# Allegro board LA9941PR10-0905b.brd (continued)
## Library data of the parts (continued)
C11 C12 CA8 CA11 CA16 CA54-CA57 CA61 CA62 CA64 CA68 CA69 CA71-CA73 CA75 CA76 CA78 CA82 CA84 CE57 CE322 CH102 CM32 CN34 CT22 CV26 CV702 CV709 CV727 CV734 CV767 CZ28 CZ29 CZ32 CZ600 CZ601 PC108 PC209 PC212 PC216 PC224 PC261 PC307 PC310 PC311 PC316 PC317 PC319 PC404 PC407 PC409 PC410 PC504 PC506 PC604 PC607 PC614 PC706-PC708 PC711 PC714 PC727 PC728 PC730 PC731 PC800 PC809 PC813 PC822 PC823 PC838 PC839 PC910-PC919 PC940-PC944 = C_0603
CA3 CA5 CA12 CA14 CA18 CA21 CA31 CA43 CA45 CA46 CA66 CA67 CA85 CA86 CA88 CA90 CI19 CI23 CV574 CV3508 CV3513 PC204-PC207 PC214 PC215 PC217 PC221-PC223 PC230-PC233 PC305 PC309 PC400 PC401 PC405 PC406 PC502 PC503 PC603 PC610-PC613 PC621 PC701-PC703 PC715-PC717 PC801-PC804 PC814-PC817 PC832-PC835 PC953-PC956 PC958 PC959 PC961-PC984 PC990 = C_0805
CA26 PC312 PC313 PC408 PC507 PC829-PC831 = C_B2
CD2-CD6 CD16-CD21 CD24-CD28 CD38-CD43 = C_0402: room: DIMMA
CD7 = C_SX: room: DIMMA
CD8-CD13 CD22 CD30-CD35 CD44 = C_0603: room: DIMMA
CE4-CE14 CE16 CE18 CE19 CE21 = C_0402: room: EC
CE17 = C_0805: room: EC
CE22 = C_0603: room: EC
CH3 CH4 CH11 CH17-CH22 CH27 CH28 CH33 CH36-CH38 CH46 CH54-CH56 CH61 CH62 CH69-CH73 CH76-CH79 CH82 CH84-CH86 CH88-CH95 = C_0402: room: PCH
CH5 CH6 CH12 CH63 CH64 CH75 CH87 = C_0603: room: PCH
CH35 CH60 CH65-CH68 CH81 = C_0805: room: PCH
CI1 = C_1206: room: USB
CI2-CI4 CI7 CI8 CI15-CI17 = C_0402: room: USB
CI9 = C_1206
CLRP1 CLRP2 = SHORTPADS: User Part Number: PART#; room: PCH
CM11-CM13 = C_0402: room: SSD
CM14 = C_0805: room: SSD
CN1-CN6 CN8-CN13 = C_0402: room: HDD
CN7 = C_0805: room: HDD
CN14 = C_0603: room: FFS
CN15 = C_0402: room: FFS
CU1-CU32 CU39 CU177 CU178 CU192-CU201 = C_0402: room: CPU
CU168 = C_D2: room: CPU
CU169-CU176 = C_0603: room: CPU
CV531-CV548 CV550-CV552 CV557-CV571 CV575 CV576 CV580 CV581 CV591-CV596 CV606-CV611 CV613 CV614 CV619 CV621-CV623 CV636-CV638 = C_0402: room: GPU
CV572 CV582-CV584 CV588-CV590 CV597-CV599 CV603-CV605 CV612 CV615-CV617 = C_0603: room: GPU
CV573 CV585-CV587 CV600-CV602 = C_0805: room: GPU
CV643 CV650 CV651 CV653-CV658 CV660-CV663 CV668 CV675 CV676 CV678-CV683 CV685-CV688 = C_0402: room: VRAM
CV652 CV659 CV677 CV684 = C_0603: room: VRAM
CV751 CV752 = C_0402: room: LVDS
CV758-CV766 = C_0402: room: HDMI
CV769 = C_0603: room: DP
CV770 CV779-CV786 CV788 = C_0402: room: DP
CV787 = C_0805: room: DP
CZ6 CZ7 = C_0402: room: DC_DC
CZ11 CZ20 CZ45 = C_0805: room: DC_DC
CZ15 CZ38 = C_0603: room: DC_DC
D8 PD102-PD104 = PESD24VS2UT_SOT23-3
DA2 DA3 = PJDLC05_SOT23-3
DA4 DA5 = PJDLC05C_SOT23-3
DE2 = PESD24VS2UT_SOT23-3: room: BUTTON
DE4 = CH751H-40PT_SOD323-2
DE5 = PESD5V0U2BT_SOT23-3: room: TP
DE6 DN2 = PESD5V0U2BT_SOT23-3
DE7-DE10 DE12-DE18 DE303-DE306 DV11 DV17-DV21 = RB751V40_SC76-2
DI1 DI6 = AZ1045-04F_DFN2510P10E-10-9: room: USB
DI2 DI5 = AZC199-02SPR7G_SOT23-3: room: USB
DI3 = PESD5V0U2BT_SOT23-3: room: USB
DPF1 HDMIF1 = F_1206L150PR
DV2-DV5 = AZ1045-04F_DFN2510P10E-10-9
DV8 DV9 = BAT1000-7-F_SOT23-3
DV10 DV13 DZ2 = BAT54CW-7-F_SOT323-3
F1 = F_NANOSMDC050F-13P2-2
FD1-FD4 = FIDUCIAL_C40M80: room: ETY-ROOM
H2 = H_2P3: room: ETY-ROOM
H3 = H_3P9: room: ETY-ROOM
H4 = H_3P7: room: ETY-ROOM
H5 = H_4P1X3P7: room: ETY-ROOM
H6 = H_3P9
H7 H14 H17 H19-H21 H23-H27 = EMIST_SUL-12A2M_1P
H8 H15 = H_3P3
H9 H11 = H_2P3
H10 = H_2P1X2P5
H12 H13 H16 = H_2P5
H18 = H_2P1
H28 H29 = CLIP_C5
HT1-HT6 HU101 PH700 PH701 PR101-PR111 PR113 PR114 PR116 PR118 PR200 PR204 PR208 PR211 PR212 PR214 PR216 PR217 PR223-PR225 PR227 PR281-PR284 PR290-PR294 PR300-PR302 PR304-PR306 PR350 PR401 PR405 PR406 PR408 PR502 PR505 PR507 PR508 PR600 PR602 PR700-PR702 PR704 PR707 PR709 PR711 PR717 PR718 PR721 PR722 PR724 PR726-PR728 PR732-PR734 PR736 PR738 PR739 PR744 PR745 PR748 PR749 PR803 PR804 PR807 PR809 PR812 PR815 PR817 PR819 PR824 PR825 PR827 PR837 PR841 PR842 PR850-PR852 R2 R10-R12 R16-R34 R47 R48 R51 R52 R59 R66 R67 R72 R2515 R2530-R2536 RA2-RA5 RA7 RA9-RA11 RA17-RA20 RA22 RA24 RA26 RA42-RA46 RA48-RA52 RA54-RA68 RA70 RA75 RA76 RA81 RA89 RA91-RA97 RA99 RA100 RA102 RE20 RE28 RE29 RE32-RE34 RE36 RE43 RE44 RE47 RE48 RE50-RE59 RE61-RE66 RE68 RE69 RE71 RE72 RE74 RE76 RE84 RE340 RE341 RE469 RH18-RH20 RH27 RH30 RH31 RH37 RH41 RH63 RH65-RH69 RH75 RH113 RH146 RH163 RH164 RH167 RH168 RH170 RH173 RH177 RH178 RH188 RH191 RH193 RH194 RH243-RH245 RH247 RH322 RH448 RH456 RH724 RH725 RI6 RI30 RI32 RI320 RI460-RI468 RN1 RN6-RN8 RN10-RN21 RN40 RN42 RT1-RT6 RTCR1 RU7 RU11-RU13 RU36 RU40 RU44 RU45 RU50 RU51 RU54 RU56 RU62 RU76 RU94 RU115 RU118 RV5 RV10-RV12 RV289 RV299 RV300 RV319 RV325 RV326 RV331 RV333 RV334 RV338-RV341 RV374 RV375 RV378-RV389 RV391 RV392 RV394-RV399 RV409 RV410 RV414 RV416-RV419 RV424 RV444 RV445 RV447-RV452 RV458-RV460 RV490 RV491 RV501 RV505-RV509 RZ9 RZ12 RZ15 RZ30 RZ38 RZ472 RZ484 RZ485 RZ600 RZ601 = R_0402
JDIMM1 JDIMM2 = BELLW_80001-1021_204P: room: DIMMA
JEDP1 = ACES_59003-04006-001_40P
JFAN1 JSPK1 = ACES_50224-00401-001_4P
JHDD = J-L_UCNR2234B020-0_20P: room: HDD
JHDMI = ACON_HMRB9-AK120C_19P-T: room: HDMI
JHP2 = SINGA_2SJ3095-001111F_6P-T
JKB = ACES_50692-03041-001_30P: room: KB
JKBL = ACES_50524-00401-001_4P-T
JMDP = ACON_MAR2H-20K1200_20P-T: room: DP
JNFC1 = HB_A531515-SCHR21_15P-T
JP2 JP6-JP14 JP17-JP19 PJP401 = JUMP_43X39
JP3-JP5 JP15 JP802 JP803 PJP300-PJP303 PJP400 PJP403 PJP404 PJP500-PJP502 PJP601 PJP602 PJP700 PJP701 PJP800 = JUMP_43X118
JSSD = ACES_50711-0520W-001_52P: room: SSD
JTB1 = HRS_DF40HC-3P0-90DS-04V_90P-T
JTP = ACES_50506-00841-P01_8P: room: TP
JTS = ACES_50208-00601-P01_6P
JUSB1 JUSB3 = TAIWI_USB019-107CRL-TWD_10P-T: room: USB
JXDP = SAMTE_BSH-030-01-L-D-A-TR_60P
L1 L2 = MURAT_BLM18AG601SN1D_L0603_2P
LA1 = MURAT_BLM21PG600SN1D_L0805_2P
LA3 = TAIYO_NRH3010T4R7MN_2P
LA5 LA6 = MURAT_BLM15GA750SN1D_2P
LA7-LA9 LA11 = MURAT_BLM18PG181SN1D_2P
LE1 LE2 = KC_FBMA-L11-160808-800LMT_2P: room: EC
LED3 = LED_12-22-Y2BHC-A30-2C_3P
LED6-LED9 = LED_LTW-270TLA_2P
LH100 = MURAT_LQM18FN4R7M00D_2P
LI1-LI4 LI7-LI9 = MURAT_DLW21SN900HQ2L_0805_4P: room: USB
LV2 = MURAT_BLM18PG181SN1D_L0603_2P: room: GPU
LV3 = MURAT_BLM18AG121SN1D_L0603_2P: room: GPU
LV7-LV10 = MURAT_DLW21SN900HQ2L_0805_4P: room: HDMI
LV14 LV21 = MURAT_BLM18PG300SN1D_2P
LV16-LV20 = MURAT_DLP11SN900HL2L_4P
PC700 PC921-PC924 = C_D2
PD100 = BAV99W-7-F_SOT323-3
PD200 = RB751V-40_SOD323-2
PD201 = BAT54HT1G_SOD323-2
PD202 = SX34H_SMA2
PJP402 PJP600 = JUMP_43X79
PL100 PL103 PL106 PL108 PL205 PL206 = KC_FBMA-L11-201209-221LMA35_2P
PL101 = MURAT_BLM15AG102SN1D_2P
PL102 PL105 PL700 PL705 = TAI-T_HCB2012KF-121T50_2P
PL203 = CYNTE_PCMB104E-2R2MS_2P
PL300 PL600 = PANAS_ETQP3W1R5WFN_2P
PL301 = TOKO_FDSD0630-H-3R3M-P3_2P
PL400 PL500 = TOKO_FDSD0630-H-1R0M-P3_2P
PL701 PL702 = TOKO_FDUE1040J-H-R36M-P3_4P
PL801-PL803 = NEC_MPC0740LR42C_2P
PQ100 = FDV301N-G_SOT23-3
PQ101 = MMST3904-7-F_SOT323-3
PQ102 = SI3457CDV-T1-GE3_TSOP6
PQ103 PQ230 = L2N7002WT1G_SC70-3
PQ200 PQ201 = MDS1521URH_SO8
PQ202 = 2N7002-7-F_SOT23-3
PQ203 PQ231 Q15-Q20 = DMN66D0LDW-7_SOT363-6
PQ204 PQ700 PQ703 PQ800-PQ802 = CSD87351Q5D_SON8-7
PQ207 = 2N7002KW_SOT323-3
PQ208 = AO4407AL_SO8
PQ300 PQ500 = MDV1528URH_PDFN33-8-5
PQ301 = MDU1516URH_POWERDFN56-8-5
PQ302 PQ501 = MDV1524URH_PDFN33-8-5
PQ303 = MDU1512RH_POWERDFN56-8-5
PQ400 = MDV1527URH_POWERDFN33-8-5
PQ401 = MDV1522URH_PDFN33-8-5
PR112 PR209 PR210 PR218 PR220 PR221 PR230 PR231 PR280 PR335 PR337 PR338 PR340 PR341 PR407 PR409 PR503 PR703 PR705 PR706 PR710 PR712 PR719 PR725 PR747 PR818 PR823 PR836 PR853 RA33 RA98 RA101 RE27 RE60 RE321 RE322 RH416 RN5 RN9 RU37 RU53 RV8 RV411 RV415 RV480-RV482 RV503 RV510 = R0402_0OHM
PR201 PR219 = R_2512_4P
PR202 PR203 R55 RA47 RA90 = R_0805
PR207 = R0603_0OHM
PR213 PR222 PR309 PR310 PR403 PR504 PR607 PR716 PR743 PR806 PR822 PR830 = R_1206
PR215 PR307 PR308 PR400 PR402 PR501 PR510 PR608 PR713-PR715 PR730 PR740-PR742 PR801 PR813 PR821 PR832 RH201 RH220 RZ602 = R_0603
PT200 PT601 T7 T8 T37-T44 T46 T81 T118 T126 T170-T178 = TPC12
PU200 = BQ24715RGRR_QFN20_3P5X3P5
PU202 = INA199A2DCKR_SC70-6
PU300 = TPS51225CRUKR_QFN20_3X3
PU400 = G5616ARZ1U_TQFN20_3X3
PU500 = RT8237EZQW-2_WDFN10_3X3
PU600 = TPS51367RVER_QFN28_4P5X3P5
PU700 = ISL95812HRZ-T_QFN32_4X4
PU800 = RT8813AGQW_WQFN24_4X4
PU801 = RT9610BZQW_WDFN8_2X2
Q11 QA2 QA5 QV24 QV25 = SSM3K7002FU_SC70-3
QA3 QA4 QV7 = 2N7002DW-T-R7_SOT363-6
QD1 QD2 = BSS138-G_SOT23-3: room: DIMMA
QE1 QH6 QV37 QV39 QV40 QZ18-QZ20 = 2N7002_SOT23-3
QH2 QH3 = 2N7002DW-T-R7_SOT363-6: room: PCH
QN2 = 2N7002DW-T-R7_SOT363-6: room: FFS
QU3 = BSS138-G_SOT23-3: room: CPU
QU7 = BSS138-G_SOT23-3
QV21 = 2N7002DW-T-R7_SOT363-6: room: GPU
QV22 QV23 = SSM3K7002FU_SC70-3: room: VRAM
QV29 = SI3457BDV-T1-E3_TSOP6: room: LVDS
QV30 = SSM3K7002FU_SC70-3: room: LVDS
QV38 = SSM3K7002FU_SC70-3: room: DP
QV42 QZ24 = 2N7002DW-7-F_SOT363-6
QZ1 = SI3456DDV-T1-GE3_TSOP6: room: DC_DC
QZ2 = 2N7002DW-T-R7_SOT363-6: room: DC_DC
QZ5 QZ17 = 2N7002DW-7-F_SOT363-6: room: DC_DC
QZ25 = AO3413_SOT23-3
R1 = R_0402: room: TPM
R8 R53 R54 R56 R58 RA53 RH202 RH213 RI74 = R0805_0OHM
RD8 RD9 RD15 RD16 = R_0402: room: DIMMA
RE9 RE11-RE13 RE38-RE40 RE42 = R_0402: room: EC
RE49 = R_0402: room: BUTTON
RH1-RH8 RH11-RH17 RH21 RH23-RH26 RH28 RH29 RH32 RH33 RH35 RH38 RH40 RH53 RH62 RH64 RH84 RH89 RH97-RH99 RH119-RH122 RH127 RH130 RH132 RH136 RH138 RH143-RH145 RH154 RH155 RH158 RH159 RH162 RH165 RH169 RH171 RH172 RH174-RH176 RH180 = R_0402: room: PCH
RH219 = R_0603: room: PCH
RI8 RI9 RI17 RI19 = R_0402: room: USB
RM12 = R_0402: room: WLAN
RN3 RN4 RN30 = R_0402: room: HDD
RN23 RN26 RN33 = R_0402: room: FFS
RPE2 RPH1 RPH2 RPH4 RPH5 RPH7-RPH9 RPH12-RPH16 RPH19 RPH24 RPH25 RPH27 RPH29 RPH30 RPH32 RPH33 = RP_0804_8P4R
RTCD1 = BAT54CW_SOT323-3
RU1 RU2 RU30 RU32 RU33 RU35 RU42 RU48 RU58-RU61 RU66-RU68 RU72-RU74 RU77 RU83-RU87 RU90 RU91 RU93 RU96 RU99 = R_0402: room: CPU
RU43 = R0402_0OHM: room: CPU
RV286 RV290 RV301-RV316 RV318 RV320 RV323 RV324 RV327-RV330 RV332 RV342-RV347 RV479 = R_0402: room: GPU
RV337 = R0603_0OHM: room: GPU
RV348 RV349 RV352-RV363 RV365 RV366 RV368-RV373 = R_0402: room: VRAM
RV403 RV405 RV408 RV412 RV413 = R_0402: room: LVDS
RV429-RV431 = R_0402: room: HDMI
RV453 RV456 RV469 RV470 = R_0402: room: DP
RZ3 RZ5 RZ8 RZ10 RZ11 = R_0402: room: DC_DC
RZ6 = R_0603: room: DC_DC
SW1 = SW_TML-3WWW-Q-T-R_6P: room: BUTTON
SW2 = SW_NTC311-EA1T-A160T_4P
T6 = TPC12: room: PCH
T11-T13 = TPC12: room: GPU
U1 = AT97SC3204-X2A14-AB_TSSOP28: room: TPM
U4 = NCT3705U-A_SOT23-5
U5 = APX9131AAI-TRG_SOT23-3
U6 = HASWELL_BGA_1364P-T
U7 = LYNXPOINT_BGA_695P-T
U11 = PS8330BQFN48GTR-A0_QFN48_7X7
U12 = ALC5505_QFN48_7X7
U15 = ALC3661-CG_MQFN48_6X6
U22 = PS8201ATQFN40GTR2A0_TQFN40_5X5
U23 = W25X20AVSNIG_SO8
UA2 = MAX9892ERTLFT_UCSP_6P
UA5 = TPA3113D2PWPR_HTSSOP28
UE1 = KB9012BF-A3_LFBGA_128P: room: EC
UE2 = SN74LVC1G06DCKR_SC70-5: room: EC
UE36 = KC3810_QFN24_4X4
UH2 = W25Q64FVSSIG_SO8: room: PCH
UH3 = MC74VHC1G08DFT2G_SC70-5: room: PCH
UH4 UH5 = SN74AHC1G08DCKR_SC70-5: room: PCH
UI5 = PS8723BTQFN32GTR-A0_TQFN32_3X6
UN1 = PS8520BTQFN20GTR2_TQFN20_4X4: room: HDD
UN2 = LNG3DMTR_LGA16_3X3: room: FFS
UN3 UV12 UZ14 = APL3512ABI-TRG_SOT23-5
US1 US2 = TPS2543RTER_QFN16_3X3
UU2 = SN74LVC1G07DCKR_SC70-5: room: CPU
UU3 = 74AHC1G09GW_TSSOP5: room: CPU
UV1 = N13M_FCBGA_908P: room: GPU
UV5 UV6 = K4G41325FC-HC04_FBGA_170P: room: VRAM
UV9 UV10 = K4G41325FC-HC04_FBGA_170P
UZ1 = SI4634DY-T1-GE3_SO8: room: DC_DC
UZ4 = TPS22966DPUR_SON14_2X3
UZ600 = G9141P11U_SO8
YA2 = Y_X3G024000DC1H_4P
YH1 = Y_FC-135_2P: room: PCH
YH2 = Y_X3G025000DA1H_4P: room: PCH
YV1 = Y_X3G025000DI1H-H_4P: room: GPU

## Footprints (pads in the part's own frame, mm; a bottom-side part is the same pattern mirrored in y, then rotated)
2N7002-7-F_SOT23-3
  oval 1.016x1.524 smd: 1(0,0) 2(0.965,2.083) 3(-0.965,2.083)
2N7002_SOT23-3
  oval 1.016x1.524 smd: 1(0,0) 2(0.965,2.083) 3(-0.965,2.083)
2N7002DW-7-F_SOT363-6
  oval 0.432x0.61 smd: 1(0,0) 2(0.65,0) 3(1.3,0) 4(1.3,1.9) 5(0.65,1.9) 6(0,1.9)
2N7002DW-T-R7_SOT363-6
  oval 0.381x1.397 smd: 1(0,0) 2(0.65,0) 3(1.3,0) 4(1.3,1.725) 5(0.65,1.725) 6(0,1.725)
2N7002KW_SOT323-3
  oval 0.813x0.914 smd: 1(0,0) 2(0.65,1.6) 3(-0.65,1.6)
74AHC1G09GW_TSSOP5
  oval 0.381x1.346 smd: 1(0,0) 2(0.65,0) 3(1.3,0) 4(1.3,1.79) 5(0,1.79)
ACES_50208-00601-P01_6P
  oval 0.508x0.991 smd: 1(0,0) 2(-0.8,0) 3(-1.6,0) 4(-2.4,0) 5(-3.2,0) 6(-4,0)
  rect 1.194x1.702 smd: 7(-5.3,-1.95) 8(1.3,-1.95)
ACES_50224-00401-001_4P
  oval 0.61x1.549 smd: 1(0,0) 2(1,0) 3(2,0) 4(3,0)
  rect 1.194x1.803 smd: 5(4.3,-3.875) 6(-1.3,-3.875)
ACES_50290-00701-001_7P-T
  rect 0.838x7.01 smd: 1(0,0) 2(1.5,0) 3(3,0) 4(4.5,0) 5(6,0) 6(7.5,0) 7(9,0)
ACES_50290-01201-P01_12P-T
  rect 0.838x7.01 smd: 1(0,0) 2(1.5,0) 3(3,0) 4(4.5,0) 5(6,0) 6(7.5,0) 7(9,0) 8(10.5,0) 9(12,0) 10(13.5,0) 11(15,0) 12(16.5,0)
ACES_50506-00841-P01_8P
  oval 0.305x0.889 smd: 1(0,0) 2(0.5,0) 3(1,0) 4(1.5,0) 5(2,0) 6(2.5,0) 7(3,0) 8(3.5,0)
  rect 0.991x2.007 smd: 9(-2.1,-3.05) 10(5.6,-3.05)
ACES_50524-00401-001_4P-T
  oval 0.305x1.295 smd: 1(0,0) 2(1,0) 3(2,0) 4(3,0)
  rect 1.803x2.21 smd: 5(5.65,-5.65) 6(-2.65,-5.65)
ACES_50692-03041-001_30P
  oval 0.305x1.295 smd: 1(0,0) 2(1,0) 3(2,0) 4(3,0) 5(4,0) 6(5,0) 7(6,0) 8(7,0) 9(8,0) 10(9,0) 11(10,0) 12(11,0) 13(12,0) 14(13,0) 15(14,0) 16(15,0) 17(16,0) 18(17,0) 19(18,0) 20(19,0) 21(20,0) 22(21,0) 23(22,0) 24(23,0) 25(24,0) 26(25,0) 27(26,0) 28(27,0) 29(28,0) 30(29,0)
  rect 1.803x2.21 smd: 31(-2.15,-5.65) 32(31.65,-5.65)
ACES_50711-0520W-001_52P
  oval 0.61x1.295 smd: 1(0,0) 3(-0.8,0) 5(-1.6,0) 7(-2.4,0) 9(-3.2,0) 11(-4,0) 13(-4.8,0) 15(-5.6,0) 17(-9.6,0) 19(-10.4,0) 21(-11.2,0) 23(-12,0) 25(-12.8,0) 27(-13.6,0) 29(-14.4,0) 31(-15.2,0) 33(-16,0) 35(-16.8,0) 37(-17.6,0) 39(-18.4,0) 41(-19.2,0) 43(-20,0) 45(-20.8,0) 47(-21.6,0) 49(-22.4,0) 51(-23.2,0)
  oval 0.61x1.397 hole 0.356x0.838: 2(-0.4,-1.5) 4(-1.2,-1.5) 6(-2,-1.5) 8(-2.8,-1.5) 10(-3.6,-1.5) 12(-4.4,-1.5) 14(-5.2,-1.5) 16(-6,-1.5) 18(-10,-1.5) 20(-10.8,-1.5) 22(-11.6,-1.5) 24(-12.4,-1.5) 26(-13.2,-1.5) 28(-14,-1.5) 30(-14.8,-1.5) 32(-15.6,-1.5) 34(-16.4,-1.5) 36(-17.2,-1.5) 38(-18,-1.5) 40(-18.8,-1.5) 42(-19.6,-1.5) 44(-20.4,-1.5) 46(-21.2,-1.5) 48(-22,-1.5) 50(-22.8,-1.5) 52(-23.6,-1.5)
  oval 0.787x2.108 hole 0.406x1.702: 53(-26.15,-8.15) 54(2.55,-8.15)
ACES_59003-04006-001_40P
  round 0.889 hole 0.889 unplated: (-20.25,2.125) (0.75,2.125)
  oval 0.254x1.143 smd: 1(0,0) 2(-0.5,0) 3(-1,0) 4(-1.5,0) 5(-2,0) 6(-2.5,0) 7(-3,0) 8(-3.5,0) 9(-4,0) 10(-4.5,0) 11(-5,0) 12(-5.5,0) 13(-6,0) 14(-6.5,0) 15(-7,0) 16(-7.5,0) 17(-8,0) 18(-8.5,0) 19(-9,0) 20(-9.5,0) 21(-10,0) 22(-10.5,0) 23(-11,0) 24(-11.5,0) 25(-12,0) 26(-12.5,0) 27(-13,0) 28(-13.5,0) 29(-14,0) 30(-14.5,0) 31(-15,0) 32(-15.5,0) 33(-16,0) 34(-16.5,0) 35(-17,0) 36(-17.5,0) 37(-18,0) 38(-18.5,0) 39(-19,0) 40(-19.5,0)
  rect 1.499x2.997 smd: 41(-22,2.125) 42(2.5,2.125)
  rect 2.794x1.499 smd: 43(-15.45,4.175) 44(-4.05,4.175)
ACON_HMRB9-AK120C_19P-T
  round 0.813 hole 0.508: 1(0,0) 2(-0.5,-1.2) 3(-1,0) 4(-1.5,-1.2) 5(-2,0) 6(-2.5,-1.2) 7(-3,0) 8(-3.5,-1.2) 9(-4,0) 10(-4.5,-1.2) 11(-5,0) 12(-5.5,-1.2) 13(-6,0) 14(-6.5,-1.2) 15(-7,0) 16(-7.5,-1.2) 17(-8,0) 18(-8.5,-1.2) 19(-9,0)
  oval 1.6x2.311 hole 0.991x1.702: 20(-11.75,0) 21(-13.5,-7.57) 22(4.5,-7.57) 23(2.75,0)
ACON_MAR2H-20K1200_20P-T
  oval 0.356x2.007 smd: 1(0,0) 3(-0.6,0) 5(-1.2,0) 7(-1.8,0) 9(-2.4,0) 11(-3,0) 13(-3.6,0) 15(-4.2,0) 17(-4.8,0) 19(-5.4,0)
  round 0.813 hole 0.508: 2(0,-3.31) 4(-0.6,-2.11) 6(-1.1,-3.31) 8(-1.7,-2.11) 10(-2.2,-3.31) 12(-3.2,-3.31) 14(-3.7,-2.11) 16(-4.3,-3.31) 18(-4.8,-2.11) 20(-5.4,-3.31)
  oval 1.194x2.388 hole 0.711x1.905: 21(-6.65,-2.91) 24(1.25,-2.91)
  oval 1.194x2.311 hole 0.711x1.803: 22(-8.2,-8.72) 23(2.8,-8.72)
ALC3661-CG_MQFN48_6X6
  oval 0.203x1.041 smd: 1(0,0) 2(0.4,0) 3(0.8,0) 4(1.2,0) 5(1.6,0) 6(2,0) 7(2.4,0) 8(2.8,0) 9(3.2,0) 10(3.6,0) 11(4,0) 12(4.4,0) 25(4.4,5.95) 26(4,5.95) 27(3.6,5.95) 28(3.2,5.95) 29(2.8,5.95) 30(2.4,5.95) 31(2,5.95) 32(1.6,5.95) 33(1.2,5.95) 34(0.8,5.95) 35(0.4,5.95) 36(0,5.95)
  oval 1.041x0.203 smd: 13(5.175,0.775) 14(5.175,1.175) 15(5.175,1.575) 16(5.175,1.975) 17(5.175,2.375) 18(5.175,2.775) 19(5.175,3.175) 20(5.175,3.575) 21(5.175,3.975) 22(5.175,4.375) 23(5.175,4.775) 24(5.175,5.175) 37(-0.775,5.175) 38(-0.775,4.775) 39(-0.775,4.375) 40(-0.775,3.975) 41(-0.775,3.575) 42(-0.775,3.175) 43(-0.775,2.775) 44(-0.775,2.375) 45(-0.775,1.975) 46(-0.775,1.575) 47(-0.775,1.175) 48(-0.775,0.775)
  rect 4.394x4.394 smd: 49(2.2,2.975)
ALC5505_QFN48_7X7
  oval 0.254x1.041 smd: 1(0,0) 2(0.5,0) 3(1,0) 4(1.5,0) 5(2,0) 6(2.5,0) 7(3,0) 8(3.5,0) 9(4,0) 10(4.5,0) 11(5,0) 12(5.5,0) 25(5.5,6.95) 26(5,6.95) 27(4.5,6.95) 28(4,6.95) 29(3.5,6.95) 30(3,6.95) 31(2.5,6.95) 32(2,6.95) 33(1.5,6.95) 34(1,6.95) 35(0.5,6.95) 36(0,6.95)
  oval 1.041x0.254 smd: 13(6.225,0.725) 14(6.225,1.225) 15(6.225,1.725) 16(6.225,2.225) 17(6.225,2.725) 18(6.225,3.225) 19(6.225,3.725) 20(6.225,4.225) 21(6.225,4.725) 22(6.225,5.225) 23(6.225,5.725) 24(6.225,6.225) 37(-0.725,6.225) 38(-0.725,5.725) 39(-0.725,5.225) 40(-0.725,4.725) 41(-0.725,4.225) 42(-0.725,3.725) 43(-0.725,3.225) 44(-0.725,2.725) 45(-0.725,2.225) 46(-0.725,1.725) 47(-0.725,1.225) 48(-0.725,0.725)
  rect 5.461x5.461 smd: 49(2.75,3.475)
AO3413_SOT23-3
  oval 1.016x1.524 smd: 1(0,0) 2(0.965,2.083) 3(-0.965,2.083)
AO4407AL_SO8
  oval 0.635x1.854 smd: 1(0,0) 2(1.27,0) 3(2.54,0) 4(3.81,0) 5(3.81,5.165) 6(2.54,5.165) 7(1.27,5.165) 8(0,5.165)
APL3512ABI-TRG_SOT23-5
  oval 0.61x1.041 smd: 1(0,0) 2(0.95,0) 3(1.9,0) 4(1.9,2.7) 5(0,2.7)
APX9131AAI-TRG_SOT23-3
  oval 1.016x1.524 smd: 1(0,0) 2(0.965,2.083) 3(-0.965,2.083)
AT97SC3204-X2A14-AB_TSSOP28
  oval 0.381x1.626 smd: 1(0,0) 2(0.65,0) 3(1.3,0) 4(1.95,0) 5(2.6,0) 6(3.25,0) 7(3.9,0) 8(4.55,0) 9(5.2,0) 10(5.85,0) 11(6.5,0) 12(7.15,0) 13(7.8,0) 14(8.45,0) 15(8.45,5.8) 16(7.8,5.8) 17(7.15,5.8) 18(6.5,5.8) 19(5.85,5.8) 20(5.2,5.8) 21(4.55,5.8) 22(3.9,5.8) 23(3.25,5.8) 24(2.6,5.8) 25(1.95,5.8) 26(1.3,5.8) 27(0.65,5.8) 28(0,5.8)
AZ1045-04F_DFN2510P10E-10-9
  oval 0.254x0.686 smd: 1(0,0) 2(0.5,0) 4(1.5,0) 5(2,0) 6(2,0.875) 7(1.5,0.875) 8(0.5,0.875) 9(0,0.875)
  oval 0.406x1.549 smd: 3(1,0.437)
AZC199-02SPR7G_SOT23-3
  oval 1.016x1.524 smd: 1(0,0) 2(0.965,2.083) 3(-0.965,2.083)
BAT54CW-7-F_SOT323-3
  oval 0.711x0.889 smd: 1(0,0) 2(-0.65,-1.9) 3(0.65,-1.9)
BAT54CW_SOT323-3
  oval 0.61x0.559 smd: 1(0,0) 2(-0.65,-1.85) 3(0.65,-1.85)
BAT54HT1G_SOD323-2
  rect 0.635x0.838 smd: 1(0,0) 2(2.22,0)
BAT1000-7-F_SOT23-3
  oval 1.016x1.524 smd: 1(0,0) 2(0.965,2.083) 3(-0.965,2.083)
BAV99W-7-F_SOT323-3
  oval 0.711x0.889 smd: 1(0,0) 2(-0.65,-1.9) 3(0.65,-1.9)
BELLW_80001-1021_204P
  round 1.092 hole 1.092 unplated: (-65.05,-4.1)
  round 1.6 hole 1.6 unplated: (1.75,-4.1)
  oval 0.356x2.007 smd: 1(0,0) 2(-0.3,-8.2) 3(-0.6,0) 4(-0.9,-8.2) 5(-1.2,0) 6(-1.5,-8.2) 7(-1.8,0) 8(-2.1,-8.2) 9(-2.4,0) 10(-2.7,-8.2) 11(-3,0) 12(-3.3,-8.2) 13(-3.6,0) 14(-3.9,-8.2) 15(-4.2,0) 16(-4.5,-8.2) 17(-4.8,0) 18(-5.1,-8.2) 19(-5.4,0) 20(-5.7,-8.2) 21(-6,0) 22(-6.3,-8.2) 23(-6.6,0) 24(-6.9,-8.2) 25(-7.2,0) 26(-7.5,-8.2) 27(-7.8,0) 28(-8.1,-8.2) 29(-8.4,0) 30(-8.7,-8.2) 31(-9,0) 32(-9.3,-8.2) 33(-9.6,0) 34(-9.9,-8.2) 35(-10.2,0) 36(-10.5,-8.2) 37(-10.8,0) 38(-11.1,-8.2) 39(-11.4,0) 40(-11.7,-8.2) 41(-12,0) 42(-12.3,-8.2) 43(-12.6,0) 44(-12.9,-8.2) 45(-13.2,0) 46(-13.5,-8.2) 47(-13.8,0) 48(-14.1,-8.2) 49(-14.4,0) 50(-14.7,-8.2) 51(-15,0) 52(-15.3,-8.2) 53(-15.6,0) 54(-15.9,-8.2) 55(-16.2,0) 56(-16.5,-8.2) 57(-16.8,0) 58(-17.1,-8.2) 59(-17.4,0) 60(-17.7,-8.2) 61(-18,0) 62(-18.3,-8.2) 63(-18.6,0) 64(-18.9,-8.2) 65(-19.2,0) 66(-19.5,-8.2) 67(-19.8,0) 68(-20.1,-8.2) 69(-20.4,0) 70(-20.7,-8.2) 71(-21,0) 72(-21.3,-8.2) 73(-24,0) 74(-24.3,-8.2) 75(-24.6,0) 76(-24.9,-8.2) 77(-25.2,0) 78(-25.5,-8.2) 79(-25.8,0) 80(-26.1,-8.2) 81(-26.4,0) 82(-26.7,-8.2) 83(-27,0) 84(-27.3,-8.2) 85(-27.6,0) 86(-27.9,-8.2) 87(-28.2,0) 88(-28.5,-8.2) 89(-28.8,0) 90(-29.1,-8.2) 91(-29.4,0) 92(-29.7,-8.2) 93(-30,0) 94(-30.3,-8.2) 95(-30.6,0) 96(-30.9,-8.2) 97(-31.2,0) 98(-31.5,-8.2) 99(-31.8,0) 100(-32.1,-8.2) 101(-32.4,0) 102(-32.7,-8.2) 103(-33,0) 104(-33.3,-8.2) 105(-33.6,0) 106(-33.9,-8.2) 107(-34.2,0) 108(-34.5,-8.2) 109(-34.8,0) 110(-35.1,-8.2) 111(-35.4,0) 112(-35.7,-8.2) 113(-36,0) 114(-36.3,-8.2) 115(-36.6,0) 116(-36.9,-8.2) 117(-37.2,0) 118(-37.5,-8.2) 119(-37.8,0) 120(-38.1,-8.2) 121(-38.4,0) 122(-38.7,-8.2) 123(-39,0) 124(-39.3,-8.2) 125(-39.6,0) 126(-39.9,-8.2) 127(-40.2,0) 128(-40.5,-8.2) 129(-40.8,0) 130(-41.1,-8.2) 131(-41.4,0) 132(-41.7,-8.2) 133(-42,0) 134(-42.3,-8.2) 135(-42.6,0) 136(-42.9,-8.2) 137(-43.2,0) 138(-43.5,-8.2) 139(-43.8,0) 140(-44.1,-8.2) 141(-44.4,0) 142(-44.7,-8.2) 143(-45,0) 144(-45.3,-8.2) 145(-45.6,0) 146(-45.9,-8.2) 147(-46.2,0) 148(-46.5,-8.2) 149(-46.8,0) 150(-47.1,-8.2) 151(-47.4,0) 152(-47.7,-8.2) 153(-48,0) 154(-48.3,-8.2) 155(-48.6,0) 156(-48.9,-8.2) 157(-49.2,0) 158(-49.5,-8.2) 159(-49.8,0) 160(-50.1,-8.2) 161(-50.4,0) 162(-50.7,-8.2) 163(-51,0) 164(-51.3,-8.2) 165(-51.6,0) 166(-51.9,-8.2) 167(-52.2,0) 168(-52.5,-8.2) 169(-52.8,0) 170(-53.1,-8.2) 171(-53.4,0) 172(-53.7,-8.2) 173(-54,0) 174(-54.3,-8.2) 175(-54.6,0) 176(-54.9,-8.2) 177(-55.2,0) 178(-55.5,-8.2) 179(-55.8,0) 180(-56.1,-8.2) 181(-56.4,0) 182(-56.7,-8.2) 183(-57,0) 184(-57.3,-8.2) 185(-57.6,0) 186(-57.9,-8.2) 187(-58.2,0) 188(-58.5,-8.2) 189(-58.8,0) 190(-59.1,-8.2) 191(-59.4,0) 192(-59.7,-8.2) 193(-60,0) 194(-60.3,-8.2) 195(-60.6,0) 196(-60.9,-8.2) 197(-61.2,0) 198(-61.5,-8.2) 199(-61.8,0) 200(-62.1,-8.2) 201(-62.4,0) 202(-62.7,-8.2) 203(-63,0) 204(-63.3,-8.2)
  rect 3.505x4.597 smd: 205(1.15,7.9) 206(-64.45,7.9)
BQ24715RGRR_QFN20_3P5X3P5
  oval 0.254x1.041 smd: 1(0,0) 2(0.5,0) 3(1,0) 4(1.5,0) 5(2,0) 11(2,3.45) 12(1.5,3.45) 13(1,3.45) 14(0.5,3.45) 15(0,3.45)
  oval 1.041x0.254 smd: 6(2.725,0.725) 7(2.725,1.225) 8(2.725,1.725) 9(2.725,2.225) 10(2.725,2.725) 16(-0.725,2.725) 17(-0.725,2.225) 18(-0.725,1.725) 19(-0.725,1.225) 20(-0.725,0.725)
  rect 2.057x2.057 smd: 21(1,1.725)
BSS138-G_SOT23-3
  oval 1.016x1.524 smd: 1(0,0) 2(0.965,2.083) 3(-0.965,2.083)
C_0402
  rect 0.508x0.559 smd: 1(0,0) 2(0.914,0)
C_0603
  rect 0.635x0.889 smd: 1(0,0) 2(1.397,0)
C_0805
  rect 0.813x1.397 smd: 1(0,0) 2(1.702,0)
C_1206
  rect 1.016x1.651 smd: 1(0,0) 2(2.667,0)
C_B2
  rect 1.346x2.692 smd: 1(0,0) 2(-2.75,0)
C_D2
  rect 2.388x2.794 smd: 1(0,0) 2(6.4,0)
C_SX
  rect 2.388x2.794 smd: 1(0,0) 2(6,0)
CH751H-40PT_SOD323-2
  rect 0.711x0.711 smd: 1(0,0) 2(2.33,0)
CLIP_C5
  round 5.004 smd: 1(0,0)
CSD87351Q5D_SON8-7
  oval 1.93x0.838 smd: 1(0,0)
  oval 0.66x0.838 smd: 2(1.905,0) 3(3.175,0) 4(3.175,5.39) 5(1.905,5.39) 6(0.635,5.39) 7(-0.635,5.39)
  custom 0.87x0.87 smd: 8(1.27,2.695)
CYNTE_PCMB104E-2R2MS_2P
  rect 3.505x3.988 smd: 1(0,0) 2(8,0)
DMN66D0LDW-7_SOT363-6
  oval 0.432x0.61 smd: 1(0,0) 2(0.65,0) 3(1.3,0) 4(1.3,1.9) 5(0.65,1.9) 6(0,1.9)
EMIST_SUL-12A2M_1P
  rect 6.909x1.194 smd: 1(0,0)
F_1206L150PR
  rect 0.991x1.803 smd: 1(0,0) 2(2.8,0)
F_NANOSMDC050F-13P2-2
  rect 0.991x1.6 smd: 1(0,0) 2(3,0)
FDV301N-G_SOT23-3
  oval 1.016x1.524 smd: 1(0,0) 2(0.965,2.083) 3(-0.965,2.083)
FIDUCIAL_C40M80
  round 1.016 smd: 1(0,0)
G5616ARZ1U_TQFN20_3X3
  oval 0.203x1.016 smd: 1(0,0) 2(0.4,0) 3(0.8,0) 4(1.2,0) 5(1.6,0) 11(1.6,2.975) 12(1.2,2.975) 13(0.8,2.975) 14(0.4,2.975) 15(0,2.975)
  oval 1.016x0.203 smd: 6(2.288,0.688) 7(2.288,1.088) 8(2.288,1.488) 9(2.288,1.888) 10(2.288,2.288) 16(-0.688,2.288) 17(-0.688,1.888) 18(-0.688,1.488) 19(-0.688,1.088) 20(-0.688,0.688)
  rect 1.6x1.6 smd: 21(0.8,1.488)
G9141P11U_SO8
  oval 0.635x1.727 smd: 1(0,0) 2(1.27,0) 3(2.54,0) 4(3.81,0) 5(3.81,5.3) 6(2.54,5.3) 7(1.27,5.3) 8(0,5.3)
H_2P1
  round 2.616 hole 2.108: 1(0,0)
H_2P1X2P5
  oval 2.616x2.997 hole 2.108x2.489: 1(0,0)
H_2P3
  round 2.819 hole 2.311: 1(0,0)
H_2P5
  round 2.997 hole 2.489: 1(0,0)
H_3P3
  round 3.81 hole 3.302: 1(0,0)
H_3P7
  round 4.216 hole 3.708: 1(0,0)
H_3P9
  round 4.42 hole 3.912: 1(0,0)
H_4P1X3P7
  oval 4.597x4.216 hole 4.089x3.708: 1(0,0)
HASWELL_BGA_1364P-T
  round 0.406 smd: A3(-1.298,0) A4(-2.11,0) A5(-2.914,0) A6(-3.777,0) A8(-4.641,0) A9(-5.504,0) A48(-31.158,0) A49(-31.955,0) A50(-32.818,0) A51(-33.631,0) A52(-34.404,0) AA7(-4.593,13.569) AA8(-5.293,13.569) AA9(-5.993,13.569) AA46(-30.016,13.769) AA47(-30.766,13.769) AB8(-4.968,14.269) AB9(-5.668,14.269) AB45(-29.591,14.469) AB46(-30.341,14.469) AB48(-31.141,14.469) AC7(-4.593,15.069) AC8(-5.293,15.069) AC9(-5.993,15.069) AC46(-30.016,15.169) AC47(-30.766,15.169) AD8(-4.968,15.769) AD9(-5.668,15.769) AD45(-29.591,15.869) AD46(-30.341,15.869) AD48(-31.141,15.869) AE7(-4.593,16.469) AE8(-5.293,16.469) AE9(-5.993,16.469) AE46(-30.016,16.569) AE47(-30.766,16.569) AF8(-4.968,17.169) AF9(-5.668,17.169) AG7(-4.593,17.869) AG8(-5.293,17.869) AG9(-5.993,17.869) AG45(-29.591,17.269) AG46(-30.341,17.269) AG48(-31.141,17.269) AH8(-4.968,18.569) AH9(-5.668,18.569) AH46(-30.016,17.969) AH47(-30.766,17.969) AJ45(-29.591,18.669) AJ46(-30.341,18.669) AJ48(-31.141,18.669) AK7(-4.593,19.269) AK8(-5.293,19.269) AK9(-5.993,19.269) AK46(-30.016,19.369) AK47(-30.766,19.369) AL8(-4.968,19.969) AL9(-5.668,19.969) AL45(-29.591,20.069) AL46(-30.341,20.069) AL48(-31.141,20.069) AM7(-4.593,20.769) AM8(-5.293,20.769) AM9(-5.993,20.769) AM46(-30.016,20.769) AM47(-30.766,20.769) AN8(-4.968,21.469) AN9(-5.668,21.469) AN10(-6.687,21.794) AN12(-7.387,21.469) AN13(-8.087,21.794) AN14(-8.787,21.469) AN15(-9.512,21.794) AN16(-10.212,21.469) AN17(-10.912,21.794) AN18(-11.612,21.469) AN19(-12.336,21.794) AN20(-13.036,21.469) AN21(-13.736,21.794) AN22(-14.436,21.469) AN23(-15.087,21.794) AN24(-15.787,21.469) AN25(-16.487,21.794) AN26(-17.137,21.469) AN27(-17.837,21.794) AN29(-18.587,21.469) AN30(-19.287,21.794) AN31(-19.987,21.469) AN32(-20.687,21.794) AN33(-21.337,21.469) AN34(-22.037,21.794) AN35(-22.737,21.469) AN36(-23.437,21.794) AN37(-24.137,21.469) AN38(-24.787,21.794) AN39(-25.487,21.469) AN40(-26.187,21.794) AN41(-26.887,21.469) AN42(-27.538,21.794) AN43(-28.188,21.469) AN44(-28.888,21.794) AN45(-29.591,21.469) AN46(-30.341,21.469) AN48(-31.141,21.469) AP7(-4.593,22.169) AP8(-5.293,22.169) AP9(-5.993,22.169) AP10(-6.687,22.494) AP12(-7.387,22.169) AP13(-8.087,22.494) AP14(-8.787,22.169) AP15(-9.512,22.494) AP16(-10.212,22.169) AP17(-10.912,22.494) AP18(-11.612,22.169) AP19(-12.336,22.494) AP20(-13.036,22.169) AP21(-13.736,22.494) AP22(-14.436,22.169) AP23(-15.087,22.494) AP24(-15.787,22.169) AP25(-16.487,22.494) AP26(-17.137,22.169) AP27(-17.837,22.494) AP29(-18.587,22.169) AP30(-19.287,22.494) AP31(-19.987,22.169) AP32(-20.687,22.494) AP33(-21.337,22.169) AP34(-22.037,22.494) AP35(-22.737,22.169) AP36(-23.437,22.494) AP37(-24.137,22.169) AP38(-24.787,22.494) AP39(-25.487,22.169) AP40(-26.187,22.494) AP41(-26.887,22.169) AP42(-27.538,22.494) AP43(-28.188,22.169) AP44(-28.888,22.494) AP46(-30.016,22.169) AP47(-30.766,22.169) AR8(-4.968,22.869) AR9(-5.668,22.869) AR12(-7.387,22.869) AR14(-8.787,22.869) AR16(-10.212,22.869) AR18(-11.612,22.869) AR20(-13.036,22.869) AR22(-14.436,22.869) AR24(-15.787,22.869) AR26(-17.137,22.869) AR29(-18.587,22.869) AR31(-19.987,22.869) AR33(-21.337,22.869) AR35(-22.737,22.869) AR37(-24.137,22.869) AR39(-25.487,22.869) AR41(-26.887,22.869) AR43(-28.188,22.869) AR45(-29.591,22.869) AR46(-30.341,22.869) AR48(-31.141,22.869) AW1(0,25.856) AY54(-35.855,26.314) B2(-0.563,0.532) B3(-1.298,0.7) B4(-2.11,0.7) B5(-3.066,0.7) B51(-33.571,0.7) B52(-34.404,0.7) B53(-35.155,0.7) BA1(0,26.72) BA54(-35.855,27.177) BB1(0,27.584) BB54(-35.855,27.877) BC1(0,28.447) BC2(-0.7,28.352) BC53(-35.155,28.463) BC54(-35.855,28.577) BD1(0,29.147) BD2(-0.731,29.186) BD3(-1.431,29.186) BD53(-35.155,29.186) BD54(-35.855,29.277) BE2(-0.731,29.886) BE3(-1.431,29.886) BE4(-2.131,29.886) BE51(-33.751,29.886) BE52(-34.455,29.886) BE53(-35.155,29.886) BF3(-1.475,30.586) BF4(-2.175,30.586) BF5(-2.875,30.586) BF6(-3.739,30.586) BF7(-4.628,30.586) BF48(-31.526,30.586) BF49(-32.39,30.586) BF50(-33.09,30.586) BF51(-33.79,30.586) BF52(-34.49,30.586) C1(0,1.319) C2(-0.7,1.319) C3(-1.438,1.405) C4(-2.152,1.4) C52(-34.41,1.425) C53(-35.155,1.461) C54(-35.855,1.461) D1(0,2.131) D2(-0.7,2.131) D3(-1.4,2.131) D53(-35.155,2.161) D54(-35.855,2.161) E1(0,2.844) E2(-0.7,3.047) E54(-35.855,2.861) F1(0,3.708) F54(-35.855,3.561) G1(0,4.571) G8(-4.942,4.271) G9(-5.643,4.271) G10(-6.343,4.271) G11(-7.037,4.592) G12(-7.773,4.267) G13(-8.51,4.592) G14(-9.272,4.267) G16(-10.034,4.592) G17(-10.821,4.267) G18(-11.583,4.592) G19(-12.371,4.267) G20(-13.133,4.592) G21(-13.945,4.267) G23(-14.707,4.592) G24(-15.52,4.267) G25(-16.282,4.592) G26(-17.095,4.267) G27(-17.857,4.592) G29(-18.619,4.267) G30(-19.356,4.592) G31(-20.143,4.267) G32(-20.905,4.592) G33(-21.692,4.267) G34(-22.48,4.592) G36(-23.276,4.267) G37(-24.089,4.642) G54(-35.855,4.266) H7(-4.593,4.957) H8(-5.293,4.957) H9(-5.993,4.957) H11(-7.037,5.292) H12(-7.773,4.967) H13(-8.51,5.292) H14(-9.272,4.967) H16(-10.034,5.292) H17(-10.821,4.967) H18(-11.583,5.292) H19(-12.371,4.967) H20(-13.133,5.292) H21(-13.945,4.967) H23(-14.707,5.292) H24(-15.52,4.967) H25(-16.282,5.292) H26(-17.095,4.967) H27(-17.857,5.292) H29(-18.619,4.967) H30(-19.356,5.292) H31(-20.143,4.967) H32(-20.905,5.292) H33(-21.692,4.967) H34(-22.48,5.292) H36(-23.276,4.967) H37(-24.089,5.342) H38(-24.826,4.967) H39(-25.613,5.342) J1(0,5.435) J8(-4.942,5.671) J9(-5.643,5.671) J10(-6.343,5.671) J12(-7.773,5.667) J14(-9.272,5.667) J17(-10.821,5.667) J19(-12.371,5.667) J21(-13.945,5.667) J24(-15.52,5.667) J26(-17.095,5.667) J29(-18.619,5.667) J31(-20.143,5.667) J33(-21.692,5.667) J36(-23.276,5.667) J37(-24.089,6.042) J38(-24.826,5.667) J39(-25.613,6.042) K7(-4.593,6.334) K8(-5.293,6.334) K9(-5.993,6.334) K38(-24.826,6.367) L8(-4.942,7.071) L9(-5.642,7.071) L37(-24.089,6.742) L38(-24.826,7.067) L39(-25.613,6.742) L40(-26.401,7.067) L43(-28.009,7.067) L44(-28.796,7.067) L46(-29.89,7.067) L47(-30.69,7.067) M7(-4.593,7.858) M8(-5.293,7.858) M9(-5.993,7.858) M37(-24.089,7.442) M38(-24.826,7.767) M39(-25.613,7.442) M40(-26.401,7.767) M42(-27.188,7.442) M43(-28.009,7.767) M44(-28.796,7.767) M45(-29.54,7.768) M46(-30.341,7.768) M48(-31.141,7.768) N8(-4.968,8.57) N9(-5.668,8.57) N37(-24.089,8.142) N38(-24.826,8.467) N39(-25.613,8.142) N40(-26.401,8.467) N42(-27.188,8.142) N43(-28.009,8.467) N44(-28.796,8.467) N46(-29.889,8.378) N47(-30.766,8.378) P7(-4.593,9.27) P8(-5.293,9.27) P9(-5.993,9.27) P45(-29.591,9.021) P46(-30.341,9.021) P48(-31.141,9.021) R8(-4.968,9.97) R9(-5.668,9.97) R46(-29.94,9.651) R47(-30.766,9.651) T45(-29.591,10.268) T46(-30.341,10.268) T48(-31.141,10.268) U7(-4.593,10.72) U8(-5.293,10.72) U9(-5.993,10.72) U46(-30.016,10.968) U47(-30.766,10.968) V8(-4.968,11.42) V9(-5.668,11.42) V45(-29.591,11.669) V46(-30.341,11.669) V48(-31.141,11.669) W7(-4.593,12.12) W8(-5.293,12.12) W9(-5.993,12.12) W46(-30.016,12.369) W47(-30.766,12.369) Y8(-4.968,12.82) Y9(-5.668,12.82) Y45(-29.591,13.069) Y46(-30.341,13.069) Y48(-31.141,13.069)
  round 0.356 smd: A10(-6.368,0) A11(-7.181,0) A12(-7.994,0) A14(-8.806,0) A15(-9.619,0) A16(-10.432,0) A17(-11.245,0) A19(-12.058,0) A20(-12.87,0) A21(-13.683,0) A22(-14.496,0) A24(-15.309,0) A25(-16.122,0) A26(-16.934,0) A27(-17.747,0) A28(-18.56,0) A30(-19.347,0) A31(-20.135,0) A32(-20.922,0) A33(-21.71,0) A34(-22.497,0) A36(-23.284,0) A37(-24.072,0) A38(-24.859,0) A39(-25.647,0) A40(-26.434,0) A42(-27.221,0) A43(-28.009,0) A44(-28.796,0) A45(-29.584,0) A46(-30.371,0) AA1(0,13.614) AB1(0,14.426) AB54(-35.855,14.071) AC1(0,15.239) AC54(-35.855,14.884) AD54(-35.855,15.696) AE1(0,16.052) AE54(-35.855,16.509) AF1(0,16.865) AG1(0,17.678) AG54(-35.855,17.322) AH1(0,18.49) AH54(-35.855,18.135) AJ54(-35.855,18.948) AK1(0,19.303) AK54(-35.855,19.76) AL1(0,20.116) AM1(0,20.929) AM54(-35.855,20.573) AN1(0,21.742) AN54(-35.855,21.386) AP54(-35.855,22.199) AR1(0,22.554) AR54(-35.855,23.012) AT1(0,23.367) AT54(-35.855,23.824) AU1(0,24.18) AV1(0,24.993) AV54(-35.855,24.637) AW54(-35.855,25.45) BF9(-5.466,30.586) BF10(-6.279,30.586) BF11(-7.092,30.586) BF12(-7.904,30.586) BF14(-8.717,30.586) BF15(-9.53,30.586) BF16(-10.343,30.586) BF17(-11.156,30.586) BF18(-11.968,30.586) BF20(-12.781,30.586) BF21(-13.594,30.586) BF22(-14.407,30.586) BF23(-15.22,30.586) BF25(-16.032,30.586) BF26(-16.845,30.586) BF27(-17.658,30.586) BF28(-18.471,30.586) BF30(-19.284,30.586) BF31(-20.096,30.586) BF32(-20.909,30.586) BF33(-21.722,30.586) BF34(-22.535,30.586) BF36(-23.348,30.586) BF37(-24.16,30.586) BF38(-24.973,30.586) BF39(-25.786,30.586) BF41(-26.599,30.586) BF42(-27.412,30.586) BF43(-28.224,30.586) BF44(-29.037,30.586) BF46(-29.85,30.586) BF47(-30.663,30.586) H54(-35.855,5.13) J54(-35.855,5.943) K1(0,6.298) L1(0,7.111) L54(-35.855,6.756) M1(0,7.924) M54(-35.855,7.568) N54(-35.855,8.381) P1(0,8.737) P54(-35.855,9.194) R1(0,9.55) R54(-35.855,10.007) T1(0,10.362) U1(0,11.175) U54(-35.855,10.82) V1(0,11.988) V54(-35.855,11.632) W54(-35.855,12.445) Y1(0,12.801) Y54(-35.855,13.258)
  round 0.533 smd: A53(-35.155,0) B54(-35.855,0.7) BE1(0,29.897) BE54(-35.855,29.977) BF2(-0.726,30.586) BF53(-35.19,30.586)
  round 0.33 smd: AA2(-0.7,13.614) AA3(-1.4,13.614) AA4(-2.1,13.614) AA5(-2.8,13.614) AA6(-3.5,13.614) AA48(-31.516,13.769) AB2(-0.7,14.426) AB3(-1.4,14.426) AB4(-2.1,14.426) AB5(-2.8,14.426) AB6(-3.5,14.426) AB7(-4.268,14.269) AB49(-32.355,14.071) AB50(-33.055,14.071) AB51(-33.755,14.071) AB52(-34.455,14.071) AB53(-35.155,14.071) AC2(-0.7,15.239) AC3(-1.4,15.239) AC4(-2.1,15.239) AC5(-2.8,15.239) AC6(-3.5,15.239) AC48(-31.516,15.169) AC49(-32.355,14.884) AC50(-33.055,14.884) AC51(-33.755,14.884) AC52(-34.455,14.884) AC53(-35.155,14.884) AD7(-4.268,15.769) AD49(-32.355,15.696) AD50(-33.055,15.696) AD51(-33.755,15.696) AD52(-34.455,15.696) AD53(-35.155,15.696) AE2(-0.7,16.052) AE3(-1.4,16.052) AE4(-2.1,16.052) AE5(-2.8,16.052) AE6(-3.5,16.052) AE48(-31.516,16.569) AE49(-32.355,16.509) AE50(-33.055,16.509) AE51(-33.755,16.509) AE52(-34.455,16.509) AE53(-35.155,16.509) AF2(-0.7,16.865) AF3(-1.4,16.865) AF4(-2.1,16.865) AF5(-2.8,16.865) AF6(-3.5,16.865) AF7(-4.268,17.169) AG2(-0.7,17.678) AG3(-1.4,17.678) AG4(-2.1,17.678) AG5(-2.8,17.678) AG6(-3.5,17.678) AG49(-32.355,17.322) AG50(-33.055,17.322) AG51(-33.755,17.322) AG52(-34.455,17.322) AG53(-35.155,17.322) AH2(-0.7,18.49) AH3(-1.4,18.49) AH4(-2.1,18.49) AH5(-2.8,18.49) AH6(-3.5,18.49) AH7(-4.268,18.569) AH48(-31.516,17.969) AH49(-32.355,18.135) AH50(-33.055,18.135) AH51(-33.755,18.135) AH52(-34.455,18.135) AH53(-35.155,18.135) AJ49(-32.355,18.948) AJ50(-33.055,18.948) AJ51(-33.755,18.948) AJ52(-34.455,18.948) AJ53(-35.155,18.948) AK2(-0.7,19.303) AK3(-1.4,19.303) AK4(-2.1,19.303) AK5(-2.8,19.303) AK6(-3.5,19.303) AK48(-31.516,19.369) AK49(-32.355,19.76) AK50(-33.055,19.76) AK51(-33.755,19.76) AK52(-34.455,19.76) AK53(-35.155,19.76) AL2(-0.7,20.116) AL3(-1.4,20.116) AL4(-2.1,20.116) AL5(-2.8,20.116) AL6(-3.5,20.116) AL7(-4.268,19.969) AM2(-0.7,20.929) AM3(-1.4,20.929) AM4(-2.1,20.929) AM5(-2.8,20.929) AM6(-3.5,20.929) AM48(-31.516,20.769) AM49(-32.355,20.573) AM50(-33.055,20.573) AM51(-33.755,20.573) AM52(-34.455,20.573) AM53(-35.155,20.573) AN2(-0.7,21.742) AN3(-1.4,21.742) AN4(-2.1,21.742) AN5(-2.8,21.742) AN6(-3.5,21.742) AN7(-4.268,21.469) AN49(-32.355,21.386) AN50(-33.055,21.386) AN51(-33.755,21.386) AN52(-34.455,21.386) AN53(-35.155,21.386) AP48(-31.516,22.169) AP49(-32.355,22.199) AP50(-33.055,22.199) AP51(-33.755,22.199) AP52(-34.455,22.199) AP53(-35.155,22.199) AR2(-0.7,22.554) AR3(-1.4,22.554) AR4(-2.1,22.554) AR5(-2.8,22.554) AR6(-3.5,22.554) AR7(-4.268,22.869) AR49(-32.228,22.91) AR50(-33.055,23.012) AR51(-33.755,23.012) AR52(-34.455,23.012) AR53(-35.155,23.012) AT2(-0.7,23.367) AT3(-1.4,23.367) AT4(-2.1,23.367) AT5(-2.8,23.367) AT6(-3.827,23.585) AT8(-4.767,23.585) AT9(-5.706,23.585) AT10(-6.646,23.585) AT12(-7.586,23.585) AT13(-8.526,23.585) AT15(-9.466,23.585) AT16(-10.405,23.585) AT18(-11.345,23.585) AT19(-12.285,23.585) AT20(-13.225,23.585) AT22(-14.165,23.585) AT23(-15.104,23.585) AT25(-16.044,23.585) AT26(-16.984,23.585) AT27(-17.924,23.585) AT29(-18.864,23.585) AT30(-19.803,23.585) AT32(-20.743,23.585) AT33(-21.683,23.585) AT35(-22.623,23.585) AT36(-23.563,23.585) AT37(-24.502,23.585) AT39(-25.442,23.585) AT40(-26.382,23.585) AT42(-27.322,23.585) AT43(-28.262,23.585) AT45(-29.201,23.585) AT46(-30.141,23.585) AT47(-31.081,23.585) AT49(-32.021,23.585) AT50(-33.055,23.824) AT51(-33.755,23.824) AT52(-34.455,23.824) AT53(-35.155,23.824) AU2(-0.7,24.18) AU3(-1.4,24.18) AU4(-2.1,24.18) AU5(-2.8,24.18) AU6(-3.827,24.285) AU8(-4.767,24.285) AU9(-5.706,24.285) AU10(-6.646,24.285) AU12(-7.586,24.285) AU13(-8.526,24.285) AU15(-9.466,24.285) AU16(-10.405,24.285) AU18(-11.345,24.285) AU19(-12.285,24.285) AU20(-13.225,24.285) AU22(-14.165,24.285) AU23(-15.104,24.285) AU25(-16.044,24.285) AU26(-16.984,24.285) AU27(-17.924,24.285) AU29(-18.864,24.285) AU30(-19.803,24.285) AU32(-20.743,24.285) AU33(-21.683,24.285) AU35(-22.623,24.285) AU36(-23.563,24.285) AU37(-24.502,24.285) AU39(-25.442,24.285) AU40(-26.382,24.285) AU42(-27.322,24.285) AU43(-28.262,24.285) AU45(-29.201,24.285) AU46(-30.141,24.285) AU47(-31.081,24.285) AU49(-32.021,24.285) AV2(-0.7,24.993) AV3(-1.4,24.993) AV4(-2.1,24.993) AV5(-2.8,24.993) AV6(-3.827,24.985) AV8(-4.767,24.985) AV9(-5.706,24.985) AV10(-6.646,24.985) AV12(-7.586,24.985) AV13(-8.526,24.985) AV15(-9.466,24.985) AV16(-10.405,24.985) AV18(-11.345,24.985) AV19(-12.285,24.985) AV20(-13.225,24.985) AV22(-14.165,24.985) AV23(-15.104,24.985) AV25(-16.044,24.985) AV26(-16.984,24.985) AV27(-17.924,24.985) AV29(-18.864,24.985) AV30(-19.803,24.985) AV32(-20.743,24.985) AV33(-21.683,24.985) AV35(-22.623,24.985) AV36(-23.563,24.985) AV37(-24.502,24.985) AV39(-25.442,24.985) AV40(-26.382,24.985) AV42(-27.322,24.985) AV43(-28.262,24.985) AV45(-29.201,24.985) AV46(-30.141,24.985) AV47(-31.081,24.985) AV49(-32.021,24.985) AV50(-33.055,24.637) AV51(-33.755,24.637) AV52(-34.455,24.637) AV53(-35.155,24.637) AW2(-0.7,25.806) AW3(-1.4,25.806) AW4(-2.1,25.806) AW5(-2.8,25.806) AW6(-3.827,25.685) AW8(-4.767,25.685) AW9(-5.706,25.685) AW10(-6.646,25.685) AW12(-7.586,25.685) AW13(-8.526,25.685) AW15(-9.466,25.685) AW16(-10.405,25.685) AW18(-11.345,25.685) AW19(-12.285,25.685) AW20(-13.225,25.685) AW22(-14.165,25.685) AW23(-15.104,25.685) AW25(-16.044,25.685) AW26(-16.984,25.685) AW27(-17.924,25.685) AW29(-18.864,25.685) AW30(-19.803,25.685) AW32(-20.743,25.685) AW33(-21.683,25.685) AW35(-22.623,25.685) AW36(-23.563,25.685) AW37(-24.502,25.685) AW39(-25.442,25.685) AW40(-26.382,25.685) AW42(-27.322,25.685) AW43(-28.262,25.685) AW45(-29.201,25.685) AW46(-30.141,25.685) AW47(-31.081,25.685) AW49(-32.021,25.685) AW50(-33.055,25.45) AW51(-33.755,25.45) AW52(-34.455,25.45) AW53(-35.155,25.45) AY6(-3.827,26.386) AY8(-4.767,26.386) AY9(-5.706,26.386) AY10(-6.646,26.386) AY12(-7.586,26.386) AY13(-8.526,26.386) AY15(-9.466,26.386) AY16(-10.405,26.386) AY18(-11.345,26.386) AY19(-12.285,26.386) AY20(-13.225,26.386) AY22(-14.165,26.386) AY23(-15.104,26.386) AY25(-16.044,26.386) AY26(-16.984,26.386) AY27(-17.924,26.386) AY29(-18.864,26.386) AY30(-19.803,26.386) AY32(-20.743,26.386) AY33(-21.683,26.386) AY35(-22.623,26.386) AY36(-23.563,26.386) AY37(-24.502,26.386) AY39(-25.442,26.386) AY40(-26.382,26.386) AY42(-27.322,26.386) AY43(-28.262,26.386) AY45(-29.201,26.386) AY46(-30.141,26.386) AY47(-31.081,26.386) AY49(-32.021,26.386) AY50(-33.055,26.263) AY51(-33.755,26.263) AY52(-34.455,26.263) AY53(-35.155,26.263) B6(-3.93,0.7) B8(-4.742,0.7) B9(-5.555,0.7) B10(-6.368,0.7) B11(-7.181,0.7) B12(-7.994,0.7) B14(-8.806,0.7) B15(-9.619,0.7) B16(-10.432,0.7) B17(-11.245,0.7) B19(-12.058,0.7) B20(-12.87,0.7) B21(-13.683,0.7) B22(-14.496,0.7) B24(-15.309,0.7) B25(-16.122,0.7) B26(-16.934,0.7) B27(-17.747,0.7) B28(-18.56,0.7) B30(-19.347,0.7) B31(-20.135,0.7) B32(-20.922,0.7) B33(-21.71,0.7) B34(-22.497,0.7) B36(-23.284,0.7) B37(-24.072,0.7) B38(-24.859,0.7) B39(-25.647,0.7) B40(-26.434,0.7) B42(-27.221,0.7) B43(-28.009,0.7) B44(-28.796,0.7) B45(-29.584,0.7) B46(-30.371,0.7) B48(-31.158,0.7) B49(-31.946,0.7) B50(-32.733,0.7) BA2(-0.7,26.618) BA3(-1.4,26.618) BA4(-2.1,26.618) BA5(-2.8,26.618) BA6(-3.827,27.086) BA8(-4.767,27.086) BA9(-5.706,27.086) BA10(-6.646,27.086) BA12(-7.586,27.086) BA13(-8.526,27.086) BA15(-9.466,27.086) BA16(-10.405,27.086) BA18(-11.345,27.086) BA19(-12.285,27.086) BA20(-13.225,27.086) BA22(-14.165,27.086) BA23(-15.104,27.086) BA25(-16.044,27.086) BA26(-16.984,27.086) BA27(-17.924,27.086) BA29(-18.864,27.086) BA30(-19.803,27.086) BA32(-20.743,27.086) BA33(-21.683,27.086) BA35(-22.623,27.086) BA36(-23.563,27.086) BA37(-24.502,27.086) BA39(-25.442,27.086) BA40(-26.382,27.086) BA42(-27.322,27.086) BA43(-28.262,27.086) BA45(-29.201,27.086) BA46(-30.141,27.086) BA47(-31.081,27.086) BA49(-32.021,27.086) BA50(-33.055,27.076) BA51(-33.755,27.076) BA52(-34.455,27.076) BA53(-35.155,27.076) BB2(-0.7,27.431) BB3(-1.4,27.431) BB4(-2.1,27.431) BB5(-2.977,27.786) BB6(-3.79,27.786) BB7(-4.653,27.786) BB9(-5.466,27.786) BB10(-6.279,27.786) BB11(-7.092,27.786) BB12(-7.904,27.786) BB14(-8.717,27.786) BB15(-9.53,27.786) BB16(-10.343,27.786) BB17(-11.156,27.786) BB18(-11.968,27.786) BB20(-12.781,27.786) BB21(-13.594,27.786) BB22(-14.407,27.786) BB23(-15.22,27.786) BB25(-16.032,27.786) BB26(-16.845,27.786) BB27(-17.658,27.786) BB28(-18.471,27.786) BB30(-19.284,27.786) BB31(-20.096,27.786) BB32(-20.909,27.786) BB33(-21.722,27.786) BB34(-22.535,27.786) BB36(-23.348,27.786) BB37(-24.16,27.786) BB38(-24.973,27.786) BB39(-25.786,27.786) BB41(-26.599,27.786) BB42(-27.412,27.786) BB43(-28.224,27.786) BB44(-29.037,27.786) BB46(-29.85,27.786) BB47(-30.663,27.786) BB48(-31.476,27.786) BB49(-32.337,27.786) BB51(-33.405,27.692) BB52(-34.105,27.692) BB53(-34.805,27.692) BC3(-1.41,28.352) BC4(-2.12,28.352) BC5(-2.977,28.486) BC6(-3.79,28.486) BC7(-4.653,28.486) BC9(-5.466,28.486) BC10(-6.279,28.486) BC11(-7.092,28.486) BC12(-7.904,28.486) BC14(-8.717,28.486) BC15(-9.53,28.486) BC16(-10.343,28.486) BC17(-11.156,28.486) BC18(-11.968,28.486) BC20(-12.781,28.486) BC21(-13.594,28.486) BC22(-14.407,28.486) BC23(-15.22,28.486) BC25(-16.032,28.486) BC26(-16.845,28.486) BC27(-17.658,28.486) BC28(-18.471,28.486) BC30(-19.284,28.486) BC31(-20.096,28.486) BC32(-20.909,28.486) BC33(-21.722,28.486) BC34(-22.535,28.486) BC36(-23.348,28.486) BC37(-24.16,28.486) BC38(-24.973,28.486) BC39(-25.786,28.486) BC41(-26.599,28.486) BC42(-27.412,28.486) BC43(-28.224,28.486) BC44(-29.037,28.486) BC46(-29.85,28.486) BC47(-30.663,28.486) BC48(-31.476,28.486) BC49(-32.337,28.486) BC50(-32.956,28.836) BC52(-34.455,28.309) BD4(-2.131,29.186) BD5(-2.977,29.186) BD6(-3.79,29.186) BD7(-4.653,29.186) BD9(-5.466,29.186) BD10(-6.279,29.186) BD11(-7.092,29.186) BD12(-7.904,29.186) BD14(-8.717,29.186) BD15(-9.53,29.186) BD16(-10.343,29.186) BD17(-11.156,29.186) BD18(-11.968,29.186) BD20(-12.781,29.186) BD21(-13.594,29.186) BD22(-14.407,29.186) BD23(-15.22,29.186) BD25(-16.032,29.186) BD26(-16.845,29.186) BD27(-17.658,29.186) BD28(-18.471,29.186) BD30(-19.284,29.186) BD31(-20.096,29.186) BD32(-20.909,29.186) BD33(-21.722,29.186) BD34(-22.535,29.186) BD36(-23.348,29.186) BD37(-24.16,29.186) BD38(-24.973,29.186) BD39(-25.786,29.186) BD41(-26.599,29.186) BD42(-27.412,29.186) BD43(-28.224,29.186) BD44(-29.037,29.186) BD46(-29.85,29.186) BD47(-30.663,29.186) BD48(-31.476,29.186) BD49(-32.339,29.186) BD50(-32.956,29.536) BD51(-33.578,29.186) BE5(-2.977,29.886) BE6(-3.79,29.886) BE7(-4.653,29.886) BE9(-5.466,29.886) BE10(-6.279,29.886) BE11(-7.092,29.886) BE12(-7.904,29.886) BE14(-8.717,29.886) BE15(-9.53,29.886) BE16(-10.343,29.886) BE17(-11.156,29.886) BE18(-11.968,29.886) BE20(-12.781,29.886) BE21(-13.594,29.886) BE22(-14.407,29.886) BE23(-15.22,29.886) BE25(-16.032,29.886) BE26(-16.845,29.886) BE27(-17.658,29.886) BE28(-18.471,29.886) BE30(-19.284,29.886) BE31(-20.096,29.886) BE32(-20.909,29.886) BE33(-21.722,29.886) BE34(-22.535,29.886) BE36(-23.348,29.886) BE37(-24.16,29.886) BE38(-24.973,29.886) BE39(-25.786,29.886) BE41(-26.599,29.886) BE42(-27.412,29.886) BE43(-28.224,29.886) BE44(-29.037,29.886) BE46(-29.85,29.886) BE47(-30.663,29.886) BE48(-31.476,29.886) BE49(-32.339,29.886) C5(-3.066,1.4) C6(-3.93,1.4) C8(-4.742,1.4) C9(-5.555,1.4) C10(-6.368,1.4) C11(-7.181,1.4) C12(-7.994,1.4) C14(-8.806,1.4) C15(-9.619,1.4) C16(-10.432,1.4) C17(-11.245,1.4) C19(-12.058,1.4) C20(-12.87,1.4) C21(-13.683,1.4) C22(-14.496,1.4) C24(-15.309,1.4) C25(-16.122,1.4) C26(-16.934,1.4) C27(-17.747,1.4) C28(-18.56,1.4) C30(-19.347,1.4) C31(-20.135,1.4) C32(-20.922,1.4) C33(-21.71,1.4) C34(-22.497,1.4) C36(-23.284,1.4) C37(-24.072,1.4) C38(-24.859,1.4) C39(-25.647,1.4) C40(-26.434,1.4) C42(-27.221,1.4) C43(-28.009,1.4) C44(-28.796,1.4) C45(-29.584,1.4) C46(-30.371,1.4) C48(-31.158,1.4) C49(-31.946,1.4) C50(-32.733,1.4) C51(-33.571,1.451) D4(-2.1,2.234) D5(-3.066,2.1) D6(-3.93,2.1) D8(-4.742,2.1) D9(-5.555,2.1) D10(-6.368,2.1) D11(-7.181,2.1) D12(-7.994,2.1) D14(-8.806,2.1) D15(-9.619,2.1) D16(-10.432,2.1) D17(-11.245,2.1) D19(-12.058,2.1) D20(-12.87,2.1) D21(-13.683,2.1) D22(-14.496,2.1) D24(-15.309,2.1) D25(-16.122,2.1) D26(-16.934,2.1) D27(-17.747,2.1) D28(-18.56,2.1) D30(-19.347,2.1) D31(-20.135,2.1) D32(-20.922,2.1) D33(-21.71,2.1) D34(-22.497,2.1) D36(-23.284,2.1) D37(-24.072,2.1) D38(-24.859,2.1) D39(-25.647,2.1) D40(-26.434,2.1) D42(-27.221,2.1) D43(-28.009,2.1) D44(-28.796,2.1) D45(-29.584,2.1) D46(-30.371,2.1) D48(-31.158,2.1) D49(-31.946,2.1) D50(-32.733,2.1) D51(-33.571,2.151) D52(-34.359,2.151) E3(-1.4,3.047) E4(-2.1,3.047) E5(-3.066,2.8) E6(-3.93,2.8) E8(-4.742,2.8) E9(-5.555,2.8) E10(-6.368,2.8) E11(-7.181,2.8) E12(-7.994,2.8) E14(-8.806,2.8) E15(-9.619,2.8) E16(-10.432,2.8) E17(-11.245,2.8) E19(-12.058,2.8) E20(-12.87,2.8) E21(-13.683,2.8) E22(-14.496,2.8) E24(-15.309,2.8) E25(-16.122,2.8) E26(-16.934,2.8) E27(-17.747,2.8) E28(-18.56,2.8) E30(-19.347,2.8) E31(-20.135,2.8) E32(-20.922,2.8) E33(-21.71,2.8) E34(-22.497,2.8) E36(-23.284,2.8) E37(-24.072,2.8) E38(-24.859,2.8) E39(-25.647,2.8) E40(-26.434,2.8) E42(-27.221,2.8) E43(-28.009,2.8) E44(-28.796,2.8) E45(-29.584,2.8) E46(-30.371,2.8) E48(-31.158,2.8) E49(-31.946,2.8) E50(-32.733,2.8) E51(-33.571,2.851) E52(-34.359,2.851) E53(-35.155,2.861) F2(-0.7,3.86) F3(-1.4,3.86) F4(-2.1,3.86) F5(-3.066,3.5) F6(-3.93,3.5) F8(-4.742,3.5) F9(-5.555,3.5) F10(-6.368,3.5) F11(-7.181,3.5) F12(-7.994,3.5) F14(-8.806,3.5) F15(-9.619,3.5) F16(-10.432,3.5) F17(-11.245,3.5) F19(-12.058,3.5) F20(-12.87,3.5) F21(-13.683,3.5) F22(-14.496,3.5) F24(-15.309,3.5) F25(-16.122,3.5) F26(-16.934,3.5) F27(-17.747,3.5) F28(-18.56,3.5) F30(-19.347,3.5) F31(-20.135,3.5) F32(-20.922,3.5) F33(-21.71,3.5) F34(-22.497,3.5) F36(-23.284,3.5) F37(-24.072,3.5) F38(-24.859,3.5) F39(-25.647,3.5) F40(-26.434,3.5) F42(-27.221,3.5) F43(-28.009,3.5) F44(-28.796,3.5) F45(-29.584,3.5) F46(-30.371,3.5) F48(-31.158,3.5) F49(-31.946,3.5) F50(-32.733,3.5) F51(-33.571,3.551) F52(-34.359,3.551) F53(-35.155,3.561) G2(-0.7,4.673) G3(-1.4,4.673) G4(-2.1,4.673) G5(-2.8,4.673) G6(-3.5,4.673) G7(-4.242,4.271) G38(-24.826,4.267) G39(-25.613,4.642) G40(-26.401,4.267) G42(-27.221,4.2) G43(-28.009,4.2) G44(-28.796,4.2) G45(-29.584,4.2) G46(-30.371,4.2) G48(-31.158,4.2) G49(-31.946,4.2) G50(-32.733,4.2) G51(-33.571,4.251) G52(-34.359,4.251) G53(-35.155,4.312) H40(-26.401,4.967) H42(-27.221,4.9) H43(-28.009,4.9) H44(-28.796,4.9) H45(-29.584,4.9) H46(-30.371,4.9) H48(-31.158,4.9) H49(-31.946,4.9) H50(-33.055,5.13) H51(-33.755,5.13) H52(-34.455,5.13) H53(-35.155,5.13) J2(-0.7,5.486) J3(-1.4,5.486) J4(-2.1,5.486) J5(-2.8,5.486) J6(-3.5,5.486) J7(-4.242,5.671) J40(-26.401,5.667) J42(-27.188,6.042) J43(-28.009,5.6) J44(-28.796,5.6) J45(-29.584,5.6) J46(-30.371,5.6) J48(-31.158,5.6) J49(-32.355,5.943) J50(-33.055,5.943) J51(-33.755,5.943) J52(-34.455,5.943) J53(-35.155,5.943) K2(-0.7,6.298) K3(-1.4,6.298) K4(-2.1,6.298) K5(-2.8,6.298) K6(-3.5,6.298) K40(-26.401,6.367) K43(-28.009,6.367) K44(-28.796,6.367) K45(-29.534,6.367) K46(-30.334,6.367) K48(-31.16,6.367) L2(-0.7,7.111) L3(-1.4,7.111) L4(-2.1,7.111) L5(-2.8,7.111) L6(-3.5,7.111) L7(-4.242,7.071) L42(-27.188,6.742) L48(-31.516,7.067) L49(-32.355,6.756) L50(-33.055,6.756) L51(-33.755,6.756) L52(-34.455,6.756) L53(-35.155,6.756) M2(-0.7,7.924) M3(-1.4,7.924) M4(-2.1,7.924) M5(-2.8,7.924) M6(-3.5,7.924) M49(-32.355,7.568) M50(-33.055,7.568) M51(-33.755,7.568) M52(-34.455,7.568) M53(-35.155,7.568) N7(-4.268,8.57) N48(-31.516,8.378) N49(-32.355,8.381) N50(-33.055,8.381) N51(-33.755,8.381) N52(-34.455,8.381) N53(-35.155,8.381) P2(-0.7,8.737) P3(-1.4,8.737) P4(-2.1,8.737) P5(-2.8,8.737) P6(-3.5,8.737) P49(-32.355,9.194) P50(-33.055,9.194) P51(-33.755,9.194) P52(-34.455,9.194) P53(-35.155,9.194) R2(-0.7,9.55) R3(-1.4,9.55) R4(-2.1,9.55) R5(-2.8,9.55) R6(-3.5,9.55) R7(-4.268,9.97) R48(-31.516,9.651) R49(-32.355,10.007) R50(-33.055,10.007) R51(-33.755,10.007) R52(-34.455,10.007) R53(-35.155,10.007) T2(-0.7,10.362) T3(-1.4,10.362) T4(-2.1,10.362) T5(-2.8,10.362) T6(-3.5,10.362) U2(-0.7,11.175) U3(-1.4,11.175) U4(-2.1,11.175) U5(-2.8,11.175) U6(-3.5,11.175) U48(-31.516,10.968) U49(-32.355,10.82) U50(-33.055,10.82) U51(-33.755,10.82) U52(-34.455,10.82) U53(-35.155,10.82) V2(-0.7,11.988) V3(-1.4,11.988) V4(-2.1,11.988) V5(-2.8,11.988) V6(-3.5,11.988) V7(-4.268,11.42) V49(-32.355,11.632) V50(-33.055,11.632) V51(-33.755,11.632) V52(-34.455,11.632) V53(-35.155,11.632) W48(-31.516,12.369) W49(-32.355,12.445) W50(-33.055,12.445) W51(-33.755,12.445) W52(-34.455,12.445) W53(-35.155,12.445) Y2(-0.7,12.801) Y3(-1.4,12.801) Y4(-2.1,12.801) Y5(-2.8,12.801) Y6(-3.5,12.801) Y7(-4.268,12.82) Y49(-32.355,13.258) Y50(-33.055,13.258) Y51(-33.755,13.258) Y52(-34.455,13.258) Y53(-35.155,13.258)
HB_A531515-SCHR21_15P-T
  oval 0.305x1.245 smd: 1(0,0) 2(0.5,0) 3(1,0) 4(1.5,0) 5(2,0) 6(2.5,0) 7(3,0) 8(3.5,0) 9(4,0) 10(4.5,0) 11(5,0) 12(5.5,0) 13(6,0) 14(6.5,0) 15(7,0)
  rect 0.991x2.007 smd: 16(-2.1,-2.875) 17(9.1,-2.875)
HRS_DF40HC-3P0-90DS-04V_90P-T
  oval 0.203x0.787 smd: 1(0,0) 2(0,-3.18) 3(0.4,0) 4(0.4,-3.18) 5(0.8,0) 6(0.8,-3.18) 7(1.2,0) 8(1.2,-3.18) 9(1.6,0) 10(1.6,-3.18) 11(2,0) 12(2,-3.18) 13(2.4,0) 14(2.4,-3.18) 15(2.8,0) 16(2.8,-3.18) 17(3.2,0) 18(3.2,-3.18) 19(3.6,0) 20(3.6,-3.18) 21(4,0) 22(4,-3.18) 23(4.4,0) 24(4.4,-3.18) 25(4.8,0) 26(4.8,-3.18) 27(5.2,0) 28(5.2,-3.18) 29(5.6,0) 30(5.6,-3.18) 31(6,0) 32(6,-3.18) 33(6.4,0) 34(6.4,-3.18) 35(6.8,0) 36(6.8,-3.18) 37(7.2,0) 38(7.2,-3.18) 39(7.6,0) 40(7.6,-3.18) 41(8,0) 42(8,-3.18) 43(8.4,0) 44(8.4,-3.18) 45(8.8,0) 46(8.8,-3.18) 47(9.2,0) 48(9.2,-3.18) 49(9.6,0) 50(9.6,-3.18) 51(10,0) 52(10,-3.18) 53(10.4,0) 54(10.4,-3.18) 55(10.8,0) 56(10.8,-3.18) 57(11.2,0) 58(11.2,-3.18) 59(11.6,0) 60(11.6,-3.18) 61(12,0) 62(12,-3.18) 63(12.4,0) 64(12.4,-3.18) 65(12.8,0) 66(12.8,-3.18) 67(13.2,0) 68(13.2,-3.18) 69(13.6,0) 70(13.6,-3.18) 71(14,0) 72(14,-3.18) 73(14.4,0) 74(14.4,-3.18) 75(14.8,0) 76(14.8,-3.18) 77(15.2,0) 78(15.2,-3.18) 79(15.6,0) 80(15.6,-3.18) 81(16,0) 82(16,-3.18) 83(16.4,0) 84(16.4,-3.18) 85(16.8,0) 86(16.8,-3.18) 87(17.2,0) 88(17.2,-3.18) 89(17.6,0) 90(17.6,-3.18)
